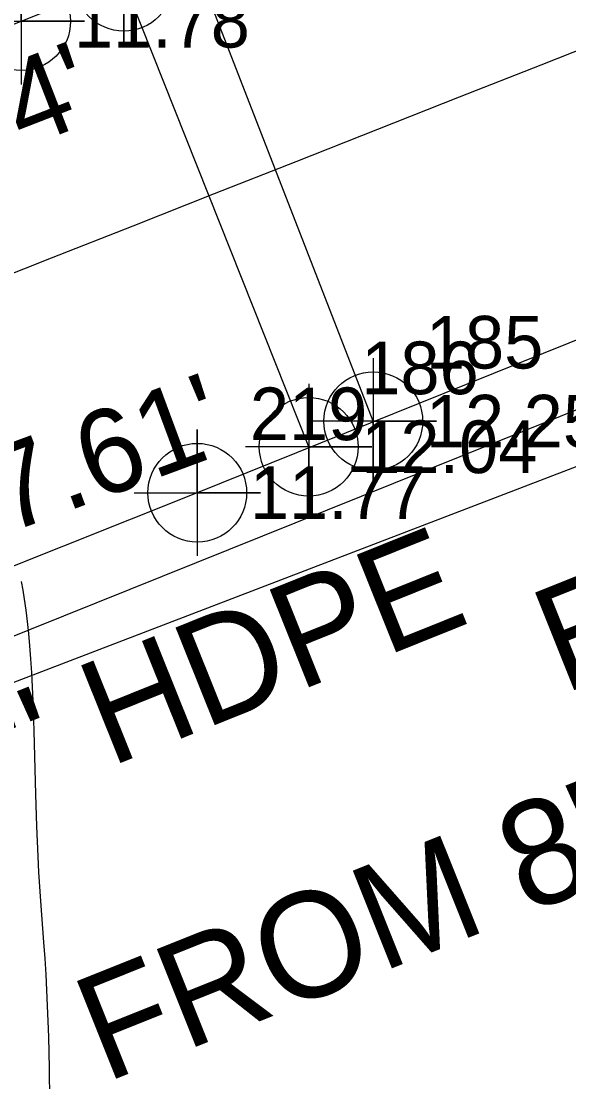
# Model space of a CAD drawing. Extents: x 2597630 to 2605918, y 617194 to 635093.
# Drawn here: x 2604083.4 to 2604109.4, y 618660.8 to 618711.2 of the extents above; entities that cross this region are included whole.
import ezdxf

# ---------------------------------------------------------------- set-up
doc = ezdxf.new("R2010")
doc.units = 0
for name, color, linetype in [('COGO Default Chain', 7, 'Continuous'), ('COGO Default Curve', 7, 'Continuous'), ('Exist Horizontal Alignment', 7, 'Continuous'), ('Exist Hydro Stream or Body of Water', 7, 'Continuous'), ('Exist Structure Major Bridge Seam', 7, 'Continuous'), ('Exist Structure Major Bridge Seam Cogo Elevation', 7, 'Continuous'), ('Exist Structure Major Bridge Seam Cogo Number', 7, 'Continuous'), ('Exist Structure Major Bridge Seam Cogo Point CELL', 7, 'Continuous'), ('Exist Structure Major Bridge Seat Top Elevation', 7, 'Continuous'), ('Exist Structure Major Deck Tunnel Box Culvert', 7, 'Continuous'), ('Exist Structure Major Deck Tunnel Box Culvert Cogo Elevation', 7, 'Continuous'), ('Exist Structure Major Deck Tunnel Box Culvert Cogo Number', 7, 'Continuous'), ('Exist Structure Major Deck Tunnel Box Culvert Cogo Point CELL', 7, 'Continuous'), ('Exist Utilities Water UG Line SUE LOS B Text', 7, 'Continuous'), ('Exist Utilities Water UG Line SUE LOS C', 7, 'Continuous'), ('Exist Utilities Water UG Line SUE LOS C Text', 7, 'Continuous')]:
    doc.layers.add(name, color=color, linetype=linetype)

# ---------------------------------------------------------------- blocks, each defined once
blk = doc.blocks.new('EXIST STRUCTURE MAJOR DECK TUNNEL BOX CULVERT COGO POINT')
at = {"layer": 'Exist Structure Major Deck Tunnel Box Culvert Cogo Point CELL'}
blk.add_lwpolyline([(-0.06, 0), (0.06, 0), (0, 0), (0, 0.06), (0, -0.06)], dxfattribs=at)
blk.add_circle((0, 0), 0.0469, dxfattribs=at)
blk = doc.blocks.new('EXIST BRIDGE SEAM COGO POINT')
at = {"layer": 'Exist Structure Major Bridge Seam Cogo Point CELL'}
blk.add_lwpolyline([(0, 0.06), (0, -0.06), (0, 0), (0.06, 0), (-0.06, 0)], dxfattribs=at)
blk.add_circle((0, 0), 0.0469, dxfattribs=at)

msp = doc.modelspace()

# ---------------------------------------------------------------- linework, layer by layer
at = {"layer": 'COGO Default Chain'}
msp.add_line((2604025.781, 618657.828), (2604635.42, 618891.582), dxfattribs=at)
msp.add_line((2604025.781, 618657.828), (2604635.42, 618891.582), dxfattribs=at)
msp.add_arc((2597632.588, 635089.507), 17613.895, 290.3221155, 292.0583016, dxfattribs=at)
msp.add_arc((2597632.588, 635089.507), 17613.895, 290.3221155, 292.0583016, dxfattribs=at)
msp.add_arc((2597632.588, 635089.507), 17613.895, 290.3221155, 292.0583016, dxfattribs=at)
msp.add_arc((2597632.588, 635089.507), 17613.895, 290.3221155, 292.0583016, dxfattribs=at)
msp.add_arc((2597632.588, 635089.507), 17613.895, 290.3221155, 292.0583016, dxfattribs=at)
msp.add_arc((2597632.588, 635089.507), 17613.895, 290.3221155, 292.0583016, dxfattribs=at)
at = {"layer": 'COGO Default Curve'}
msp.add_arc((2597632.588, 635089.507), 17613.895, 290.3221155, 292.0583016, dxfattribs=at)
msp.add_arc((2597632.588, 635089.507), 17613.895, 290.3221155, 292.0583016, dxfattribs=at)
at = {"layer": 'Exist Horizontal Alignment'}
msp.add_arc((2597632.588, 635089.507), 17613.895, 290.3221155, 292.0583016, dxfattribs=at)
at = {"layer": 'Exist Hydro Stream or Body of Water'}
msp.add_lwpolyline([(2604083.41, 618684.573), (2604083.483, 618684.153), (2604083.55, 618683.733), (2604083.626, 618683.21), (2604083.694, 618682.67), (2604083.754, 618682.107), (2604083.808, 618681.517), (2604083.856, 618680.893), (2604083.897, 618680.231), (2604083.957, 618678.906), (2604084.004, 618677.473), (2604084.086, 618674.449), (2604084.134, 618672.943), (2604084.198, 618671.496), (2604084.239, 618670.764), (2604084.333, 618669.375), (2604084.477, 618667.429), (2604084.529, 618666.657), (2604084.575, 618665.898), (2604084.615, 618665.15), (2604084.649, 618664.408), (2604084.677, 618663.671), (2604084.701, 618662.936), (2604084.733, 618661.438), (2604084.751, 618659.9)], dxfattribs=at)
at = {"layer": 'Exist Structure Major Bridge Seam'}
for p, q in [((2604100.142, 618692.192), (2604091.533, 618714.355)), ((2604097.072, 618690.973), (2604088.291, 618713.072))]:
    msp.add_line(p, q, dxfattribs=at)
at = {"layer": 'Exist Structure Major Deck Tunnel Box Culvert'}
for p, q in [((2604083.412, 618711.197), (2604113.784, 618723.45)), ((2604083.412, 618711.197), (2604113.784, 618723.45)), ((2604052.256, 618698.794), (2604083.412, 618711.197)), ((2604052.256, 618698.794), (2604083.412, 618711.197)), ((2604118.04, 618699.364), (2604091.779, 618688.789)), ((2604118.04, 618699.364), (2604091.779, 618688.789)), ((2604091.779, 618688.789), (2604066.702, 618678.789)), ((2604091.779, 618688.789), (2604066.702, 618678.789))]:
    msp.add_line(p, q, dxfattribs=at)
at = {"layer": 'Exist Utilities Water UG Line SUE LOS C'}
msp.add_line((2604045.533, 618666.916), (2604610.82, 618894.017), dxfattribs=at)

# ---------------------------------------------------------------- block references
at = {"layer": 'Exist Structure Major Bridge Seam Cogo Point CELL', "xscale": 50, "yscale": 50}
for p in [(2604088.291, 618713.072), (2604100.142, 618692.192), (2604097.072, 618690.973)]:
    msp.add_blockref('EXIST BRIDGE SEAM COGO POINT', p, dxfattribs=at)
at = {"layer": 'Exist Structure Major Deck Tunnel Box Culvert Cogo Point CELL', "xscale": 50, "yscale": 50}
for p in [(2604083.412, 618711.197), (2604083.412, 618711.197), (2604091.779, 618688.789), (2604091.779, 618688.789)]:
    msp.add_blockref('EXIST STRUCTURE MAJOR DECK TUNNEL BOX CULVERT COGO POINT', p, dxfattribs=at)

# ---------------------------------------------------------------- texts
at = {"layer": 'Exist Structure Major Bridge Seam Cogo Elevation'}
for s, p in [('12.25', (2604102.642, 618690.942)), ('12.04', (2604099.572, 618689.723))]:
    msp.add_text(s, height=2.5, dxfattribs=at).set_placement(p)
at = {"layer": 'Exist Structure Major Bridge Seam Cogo Number'}
for s, p in [('185', (2604102.642, 618694.692)), ('186', (2604099.572, 618693.473))]:
    msp.add_text(s, height=2.5, dxfattribs=at).set_placement(p)
at = {"layer": 'Exist Structure Major Bridge Seat Top Elevation'}
for s, rotation, p in [("BS1=7.64'", 21.2098, (2604064.244, 618697.666)), ("BS2=7.61'", 20.3433, (2604070.321, 618682.231))]:
    msp.add_text(s, height=4, rotation=rotation, dxfattribs=at).set_placement(p)
at = {"layer": 'Exist Structure Major Deck Tunnel Box Culvert Cogo Elevation'}
for s, p in [('11.78', (2604085.912, 618709.947)), ('11.77', (2604094.279, 618687.539))]:
    msp.add_text(s, height=2.5, dxfattribs=at).set_placement(p)
at = {"layer": 'Exist Structure Major Deck Tunnel Box Culvert Cogo Number'}
msp.add_text('219', height=2.5, dxfattribs=at).set_placement((2604094.279, 618691.289))
at = {"layer": 'Exist Utilities Water UG Line SUE LOS B Text'}
for s, p in [('EXACT LOCATION OF TRANSITION ', (2604109.182, 618679.202)), (' FROM 8" PVC TO 8" DIP TO 10" HDPE UNKNOWN', (2604085.69, 618660.048))]:
    msp.add_text(s, height=5, rotation=21.8144, dxfattribs=at).set_placement(p)
at = {"layer": 'Exist Utilities Water UG Line SUE LOS C Text'}
msp.add_text('10" HDPE', height=5, rotation=21.8876, dxfattribs=at).set_placement((2604076.791, 618671.391))

doc.saveas('drawing.dxf')
